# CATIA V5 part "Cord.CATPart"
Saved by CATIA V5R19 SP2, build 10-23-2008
Part number: Cord
Revision: ANY
Definition: UNKNOWN
Nomenclature: Cord
Source: Unknown
Bounding box of the stored display mesh (mm): x 0 to 73.5, y -90 to 3.5, z -3.5 to 3.5
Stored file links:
  Z:\fausse table rondelle-20220905T211342Z-001\fausse table rondelle\Cord.CATPart
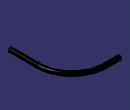
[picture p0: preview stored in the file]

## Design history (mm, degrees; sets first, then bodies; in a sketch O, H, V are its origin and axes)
AxisSystem1: origin (0, 0, 0), X (1, 0, 0), Y (0, 1, 0), Z (0, 0, 1)
Body1 "Austragung1" (main body)
  Solid1: solid without history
